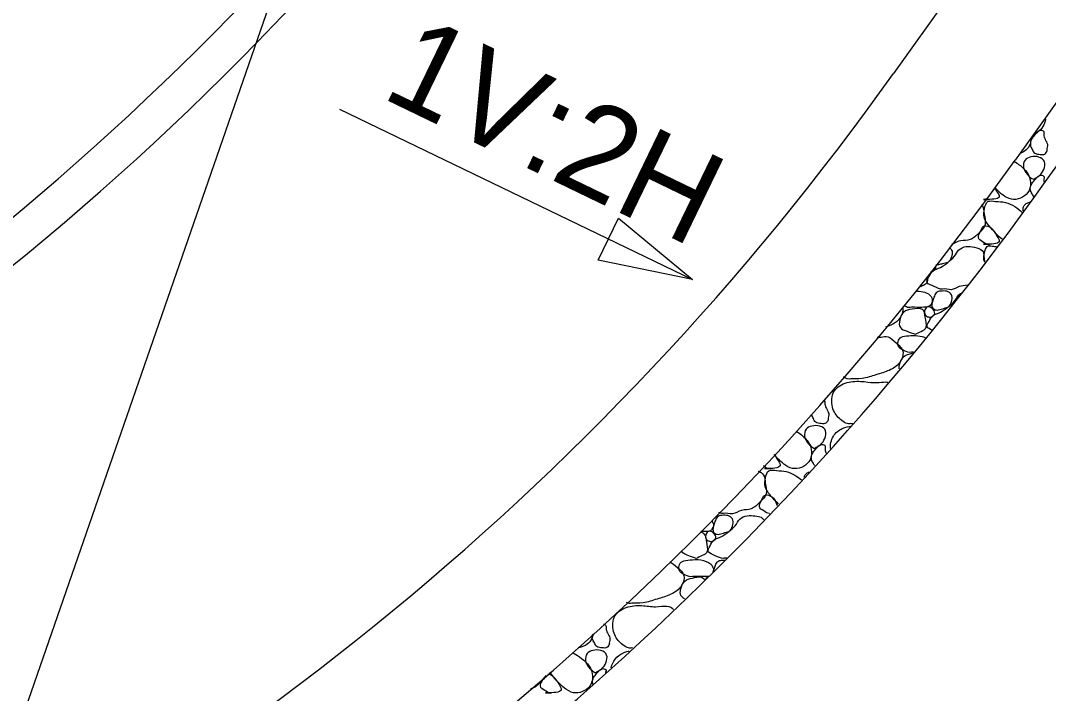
# Model space of a CAD drawing. Extents: x 1385284 to 1385995, y 1975154 to 1975620.
# Drawn here: x 1385446.25 to 1385473.8, y 1975451.07 to 1975469.11 of the extents above; entities that cross this region are included whole.
import ezdxf

# ---------------------------------------------------------------- set-up
doc = ezdxf.new("R2010")
doc.units = 0
for name, color, linetype in [('Default', 7, 'Continuous'), ('R_Horz Alg', 7, 'Continuous'), ('R_Proposed Const Limits', 7, 'Continuous'), ('R_Proposed Road', 7, 'Continuous')]:
    doc.layers.add(name, color=color, linetype=linetype)

msp = doc.modelspace()

# ---------------------------------------------------------------- linework, layer by layer
at = {"layer": 'Default'}
for p, q in [((1385500.579, 1975504.251), (1385472.911, 1975465.371)), ((1385473.726, 1975464.791), (1385501.394, 1975503.671)), ((1385459.101, 1975487.359), (1385417.983, 1975368.797)), ((1385454.799, 1975466.738), (1385464.257, 1975462.164))]:
    msp.add_line(p, q, dxfattribs=at)
msp.add_lwpolyline([(1385462.279, 1975463.815), (1385464.257, 1975462.164), (1385461.734, 1975462.69)], close=True, dxfattribs=at)
for centre, radius, start in [((1385398.122, 1975521.532), 75, 293.41039), ((1385398.122, 1975521.532), 76, 293.41039), ((1385408.545, 1975511.176), 79, 298.55327), ((1385408.545, 1975511.176), 80, 298.5224)]:
    msp.add_arc(centre, radius, start, 324.56338, dxfattribs=at)
for points in [[(1385473.713, 1975466.498), (1385473.731, 1975466.449), (1385473.682, 1975466.305), (1385473.574, 1975466.148), (1385473.47, 1975466.1), (1385473.444, 1975466.09)], [(1385473.771, 1975465.621), (1385473.76, 1975465.596), (1385473.712, 1975465.506), (1385473.59, 1975465.521), (1385473.411, 1975465.54), (1385473.374, 1975465.656), (1385473.299, 1975465.765), (1385473.338, 1975465.929), (1385473.433, 1975466.04), (1385473.51, 1975466.129), (1385473.59, 1975466.185), (1385473.714, 1975466.134), (1385473.671, 1975466.017), (1385473.733, 1975465.891), (1385473.816, 1975465.755), (1385473.752, 1975465.651), (1385473.771, 1975465.621)], [(1385473.444, 1975466.09), (1385473.437, 1975466.071), (1385473.423, 1975466.064), (1385473.405, 1975466.065)], [(1385473.327, 1975465.956), (1385473.339, 1975465.895), (1385473.3, 1975465.726), (1385473.175, 1975465.609), (1385473.064, 1975465.557), (1385473.035, 1975465.546)], [(1385472.883, 1975465.335), (1385472.89, 1975465.33), (1385472.997, 1975465.266), (1385473.196, 1975465.105), (1385473.344, 1975464.846), (1385473.306, 1975464.529), (1385473.12, 1975464.356), (1385472.952, 1975464.312), (1385472.867, 1975464.313)], [(1385473.444, 1975464.887), (1385473.413, 1975464.813), (1385473.209, 1975464.994), (1385473.107, 1975465.173), (1385473.157, 1975465.393), (1385473.321, 1975465.465), (1385473.548, 1975465.473), (1385473.738, 1975465.348), (1385473.687, 1975465.109), (1385473.574, 1975464.945), (1385473.47, 1975464.897), (1385473.444, 1975464.887)], [(1385473.414, 1975464.379), (1385473.396, 1975464.403), (1385473.367, 1975464.465), (1385473.299, 1975464.562), (1385473.338, 1975464.726), (1385473.433, 1975464.837), (1385473.51, 1975464.926), (1385473.59, 1975464.982), (1385473.714, 1975464.931), (1385473.663, 1975464.843), (1385473.687, 1975464.79), (1385473.701, 1975464.758)], [(1385472.354, 1975464.634), (1385472.37, 1975464.599), (1385472.408, 1975464.525), (1385472.59, 1975464.304), (1385471.84, 1975464.321), (1385472.226, 1975464.311), (1385472.218, 1975464.313)], [(1385472.867, 1975464.313), (1385472.796, 1975464.31), (1385472.613, 1975464.394), (1385472.475, 1975464.522), (1385472.385, 1975464.616), (1385472.361, 1975464.643)], [(1385472.012, 1975464.18), (1385472.068, 1975464.103), (1385472.067, 1975463.931), (1385472.152, 1975463.623), (1385471.938, 1975463.416), (1385471.716, 1975463.193), (1385471.44, 1975463.226), (1385471.268, 1975463.126), (1385471.204, 1975463.108), (1385471.202, 1975463.108)], [(1385472.56, 1975463.247), (1385472.515, 1975463.283), (1385472.393, 1975463.4), (1385472.206, 1975463.597), (1385472.048, 1975463.837), (1385472.08, 1975464.063), (1385472.151, 1975464.305), (1385472.38, 1975464.253), (1385472.65, 1975464.258), (1385472.911, 1975464.127), (1385473.041, 1975464.024), (1385473.1, 1975463.963)], [(1385472.184, 1975464.313), (1385472.165, 1975464.313), (1385472.144, 1975464.319), (1385472.124, 1975464.329)], [(1385473.125, 1975463.996), (1385473.124, 1975464), (1385473.114, 1975464.05), (1385473.157, 1975464.19), (1385473.252, 1975464.226), (1385473.31, 1975464.244), (1385473.313, 1975464.245)], [(1385472.184, 1975463.11), (1385472.137, 1975463.109), (1385472.041, 1975463.182), (1385471.878, 1975463.275), (1385471.987, 1975463.46), (1385472.035, 1975463.625), (1385472.216, 1975463.599), (1385472.336, 1975463.494), (1385472.403, 1975463.35), (1385472.59, 1975463.101), (1385471.84, 1975463.118), (1385472.226, 1975463.108), (1385472.218, 1975463.11)], [(1385470.958, 1975461.907), (1385470.887, 1975461.902), (1385470.751, 1975461.982), (1385470.491, 1975462.071), (1385470.605, 1975462.24), (1385470.685, 1975462.427), (1385470.909, 1975462.471), (1385471.11, 1975462.63), (1385471.289, 1975462.772), (1385471.384, 1975462.978), (1385471.595, 1975463.071), (1385471.81, 1975463.045), (1385472.074, 1975462.959), (1385472.062, 1975462.789), (1385472.09, 1975462.668), (1385472.096, 1975462.634)], [(1385471.139, 1975463.024), (1385471.172, 1975463.007), (1385471.238, 1975462.934), (1385471.214, 1975462.774), (1385471.154, 1975462.657), (1385471.101, 1975462.627)], [(1385472.095, 1975462.633), (1385472.09, 1975462.647), (1385472.056, 1975462.724), (1385472.08, 1975462.86), (1385472.151, 1975463.102), (1385472.299, 1975463.056), (1385472.384, 1975463.052), (1385472.411, 1975463.05)], [(1385470.764, 1975462.528), (1385470.787, 1975462.498), (1385470.774, 1975462.436), (1385470.707, 1975462.39), (1385470.673, 1975462.361)], [(1385471.101, 1975462.627), (1385471.054, 1975462.612), (1385470.957, 1975462.589), (1385470.851, 1975462.558), (1385470.793, 1975462.553), (1385470.783, 1975462.553)], [(1385470.551, 1975462.247), (1385470.571, 1975462.18), (1385470.544, 1975462.046), (1385470.417, 1975461.996), (1385470.347, 1975461.962), (1385470.33, 1975461.954)], [(1385470.673, 1975462.361), (1385470.661, 1975462.361), (1385470.65, 1975462.361), (1385470.638, 1975462.361)], [(1385471.63, 1975462.016), (1385471.549, 1975462.003), (1385471.402, 1975462.002), (1385471.203, 1975461.848), (1385471.037, 1975461.927), (1385470.958, 1975461.907)], [(1385470.259, 1975461.86), (1385470.298, 1975461.858), (1385470.44, 1975461.849), (1385470.652, 1975461.768), (1385470.711, 1975461.582), (1385470.615, 1975461.416), (1385470.41, 1975461.423), (1385470.249, 1975461.418), (1385470.13, 1975461.424)], [(1385470.682, 1975460.807), (1385470.628, 1975460.836), (1385470.507, 1975460.89), (1385470.605, 1975461.037), (1385470.685, 1975461.224), (1385470.909, 1975461.268), (1385471.11, 1975461.427), (1385471.289, 1975461.569), (1385471.363, 1975461.736), (1385471.44, 1975461.788), (1385471.468, 1975461.803)], [(1385471.101, 1975461.424), (1385471.054, 1975461.409), (1385470.957, 1975461.386), (1385470.823, 1975461.332), (1385470.696, 1975461.374), (1385470.669, 1975461.48), (1385470.699, 1975461.594), (1385470.743, 1975461.721), (1385470.803, 1975461.846), (1385470.954, 1975461.862), (1385471.126, 1975461.858), (1385471.238, 1975461.731), (1385471.214, 1975461.571), (1385471.154, 1975461.454), (1385471.101, 1975461.424)], [(1385469.89, 1975461.418), (1385469.916, 1975461.315), (1385469.825, 1975461.1), (1385469.63, 1975460.956), (1385469.5, 1975460.907), (1385469.438, 1975460.886)], [(1385470.235, 1975460.704), (1385470.163, 1975460.714), (1385470.018, 1975460.783), (1385469.795, 1975460.854), (1385469.798, 1975461.082), (1385469.908, 1975461.328), (1385470.124, 1975461.377), (1385470.485, 1975461.407), (1385470.488, 1975461.165), (1385470.57, 1975460.854), (1385470.386, 1975460.776), (1385470.283, 1975460.728), (1385470.235, 1975460.704)], [(1385470.13, 1975461.424), (1385470.074, 1975461.4), (1385469.999, 1975461.431), (1385469.935, 1975461.463), (1385469.93, 1975461.466)], [(1385470.673, 1975461.158), (1385470.636, 1975461.158), (1385470.551, 1975461.156), (1385470.472, 1975461.237), (1385470.48, 1975461.355), (1385470.564, 1975461.458), (1385470.691, 1975461.407), (1385470.795, 1975461.247), (1385470.707, 1975461.187), (1385470.673, 1975461.158)], [(1385469.212, 1975460.619), (1385469.217, 1975460.619), (1385469.305, 1975460.613), (1385469.506, 1975460.676), (1385469.709, 1975460.471), (1385469.962, 1975460.267), (1385469.836, 1975459.906), (1385469.547, 1975459.716), (1385469.179, 1975459.616), (1385468.808, 1975459.487), (1385468.574, 1975459.502), (1385468.502, 1975459.505)], [(1385470.13, 1975460.221), (1385470.074, 1975460.197), (1385469.929, 1975460.255), (1385469.768, 1975460.341), (1385469.757, 1975460.508), (1385469.834, 1975460.639), (1385470.053, 1975460.658), (1385470.293, 1975460.677), (1385470.468, 1975460.624), (1385470.509, 1975460.603)], [(1385469.8, 1975459.767), (1385469.795, 1975459.799), (1385469.808, 1975459.907), (1385469.908, 1975460.125), (1385470.063, 1975460.161), (1385470.151, 1975460.189), (1385470.161, 1975460.192)], [(1385470.184, 1975460.219), (1385470.166, 1975460.219), (1385470.148, 1975460.22), (1385470.13, 1975460.221)], [(1385468.502, 1975458.302), (1385468.434, 1975458.268), (1385468.211, 1975458.405), (1385467.996, 1975458.65), (1385467.967, 1975459.168), (1385468.344, 1975459.424), (1385468.78, 1975459.453), (1385469.14, 1975459.38), (1385469.403, 1975459.431), (1385469.491, 1975459.413), (1385469.498, 1975459.411)], [(1385468.502, 1975459.505), (1385468.447, 1975459.477), (1385468.373, 1975459.511), (1385468.309, 1975459.555)], [(1385467.776, 1975458.926), (1385467.782, 1975458.921), (1385467.821, 1975458.894), (1385467.802, 1975458.799), (1385467.864, 1975458.673), (1385467.946, 1975458.537), (1385467.883, 1975458.433), (1385467.901, 1975458.403)], [(1385467.901, 1975458.403), (1385467.891, 1975458.378), (1385467.843, 1975458.288), (1385467.721, 1975458.303), (1385467.542, 1975458.322), (1385467.505, 1975458.437), (1385467.466, 1975458.509), (1385467.453, 1975458.545)], [(1385467.044, 1975458.098), (1385467.138, 1975458.04), (1385467.328, 1975457.884), (1385467.474, 1975457.628), (1385467.436, 1975457.311), (1385467.251, 1975457.138), (1385467.082, 1975457.094), (1385466.998, 1975457.095)], [(1385467.575, 1975457.669), (1385467.544, 1975457.595), (1385467.339, 1975457.776), (1385467.237, 1975457.955), (1385467.288, 1975458.175), (1385467.452, 1975458.248), (1385467.679, 1975458.255), (1385467.869, 1975458.13), (1385467.818, 1975457.892), (1385467.705, 1975457.727), (1385467.601, 1975457.679), (1385467.575, 1975457.669)], [(1385467.97, 1975457.62), (1385467.942, 1975457.727), (1385468.014, 1975458.002), (1385468.27, 1975458.188), (1385468.465, 1975458.228), (1385468.499, 1975458.233)], [(1385468.555, 1975458.299), (1385468.537, 1975458.3), (1385468.52, 1975458.301), (1385468.502, 1975458.302)], [(1385467.54, 1975457.168), (1385467.525, 1975457.19), (1385467.497, 1975457.25), (1385467.43, 1975457.344), (1385467.469, 1975457.508), (1385467.564, 1975457.62), (1385467.64, 1975457.708), (1385467.72, 1975457.764), (1385467.845, 1975457.713), (1385467.798, 1975457.609), (1385467.832, 1975457.542), (1385467.85, 1975457.494)], [(1385466.453, 1975457.476), (1385466.486, 1975457.422), (1385466.534, 1975457.333), (1385466.721, 1975457.086), (1385465.971, 1975457.103), (1385466.357, 1975457.093), (1385466.349, 1975457.095)], [(1385466.998, 1975457.095), (1385466.926, 1975457.092), (1385466.744, 1975457.176), (1385466.589, 1975457.32), (1385466.487, 1975457.429), (1385466.449, 1975457.472)], [(1385466.025, 1975457.027), (1385466.066, 1975457.02), (1385466.203, 1975456.932), (1385466.197, 1975456.716), (1385466.283, 1975456.405), (1385466.069, 1975456.198), (1385465.847, 1975455.976), (1385465.57, 1975456.008), (1385465.333, 1975455.833), (1385465.168, 1975455.912), (1385465.089, 1975455.892)], [(1385466.315, 1975457.095), (1385466.268, 1975457.094), (1385466.215, 1975457.133), (1385466.165, 1975457.169), (1385466.163, 1975457.171)], [(1385466.566, 1975456.144), (1385466.487, 1975456.224), (1385466.336, 1975456.379), (1385466.178, 1975456.619), (1385466.21, 1975456.845), (1385466.281, 1975457.087), (1385466.51, 1975457.035), (1385466.78, 1975457.04), (1385467.018, 1975456.92), (1385467.137, 1975456.832), (1385467.182, 1975456.792)], [(1385467.254, 1975456.868), (1385467.259, 1975456.891), (1385467.298, 1975456.96), (1385467.35, 1975456.992), (1385467.387, 1975457.007)], [(1385466.315, 1975455.892), (1385466.268, 1975455.891), (1385466.172, 1975455.964), (1385466.009, 1975456.057), (1385466.118, 1975456.242), (1385466.166, 1975456.407), (1385466.347, 1975456.381), (1385466.466, 1975456.276), (1385466.505, 1975456.164), (1385466.529, 1975456.106), (1385466.529, 1975456.106)], [(1385465.089, 1975455.892), (1385465.049, 1975455.889), (1385465.009, 1975455.899), (1385464.969, 1975455.916)], [(1385466.328, 1975455.894), (1385466.322, 1975455.894), (1385466.303, 1975455.893), (1385466.319, 1975455.891), (1385466.325, 1975455.891)], [(1385464.762, 1975455.698), (1385464.762, 1975455.698), (1385464.812, 1975455.647), (1385464.842, 1975455.567), (1385464.746, 1975455.401), (1385464.615, 1975455.409), (1385464.53, 1975455.407), (1385464.485, 1975455.407)], [(1385465.089, 1975454.689), (1385465.017, 1975454.684), (1385464.882, 1975454.764), (1385464.622, 1975454.854), (1385464.736, 1975455.022), (1385464.815, 1975455.209), (1385465.04, 1975455.254), (1385465.24, 1975455.412), (1385465.419, 1975455.554), (1385465.514, 1975455.76), (1385465.726, 1975455.853), (1385465.941, 1975455.827), (1385466.117, 1975455.803), (1385466.157, 1975455.738), (1385466.165, 1975455.723)], [(1385465.231, 1975455.409), (1385465.184, 1975455.394), (1385465.088, 1975455.371), (1385464.953, 1975455.317), (1385464.827, 1975455.359), (1385464.8, 1975455.465), (1385464.83, 1975455.579), (1385464.873, 1975455.706), (1385464.934, 1975455.831), (1385465.084, 1975455.847), (1385465.256, 1975455.843), (1385465.369, 1975455.716), (1385465.345, 1975455.556), (1385465.284, 1975455.439), (1385465.231, 1975455.409)], [(1385464.481, 1975455.403), (1385464.504, 1975455.397), (1385464.622, 1975455.321), (1385464.619, 1975455.15), (1385464.701, 1975454.839), (1385464.517, 1975454.762), (1385464.414, 1975454.713), (1385464.365, 1975454.689)], [(1385464.804, 1975455.143), (1385464.766, 1975455.143), (1385464.682, 1975455.141), (1385464.602, 1975455.223), (1385464.611, 1975455.341), (1385464.695, 1975455.443), (1385464.822, 1975455.392), (1385464.925, 1975455.232), (1385464.838, 1975455.172), (1385464.804, 1975455.143)], [(1385464.365, 1975454.689), (1385464.293, 1975454.699), (1385464.149, 1975454.768), (1385464.017, 1975454.813), (1385463.963, 1975454.879), (1385463.959, 1975454.884)], [(1385463.65, 1975454.593), (1385463.715, 1975454.568), (1385463.85, 1975454.445), (1385464.092, 1975454.252), (1385463.967, 1975453.892), (1385463.678, 1975453.701), (1385463.31, 1975453.601), (1385462.938, 1975453.472), (1385462.705, 1975453.487), (1385462.633, 1975453.49)], [(1385464.26, 1975454.206), (1385464.205, 1975454.182), (1385464.06, 1975454.24), (1385463.898, 1975454.326), (1385463.888, 1975454.493), (1385463.965, 1975454.625), (1385464.184, 1975454.643), (1385464.484, 1975454.673), (1385464.782, 1975454.55), (1385464.831, 1975454.376), (1385464.818, 1975454.32), (1385464.818, 1975454.318)], [(1385464.814, 1975454.314), (1385464.82, 1975454.339), (1385464.838, 1975454.4), (1385464.873, 1975454.503), (1385464.934, 1975454.628), (1385465.041, 1975454.638), (1385465.106, 1975454.641), (1385465.134, 1975454.639)], [(1385465.184, 1975454.691), (1385465.151, 1975454.695), (1385465.119, 1975454.697), (1385465.089, 1975454.689)], [(1385464.055, 1975453.602), (1385464.026, 1975453.618), (1385463.925, 1975453.678), (1385463.928, 1975453.864), (1385464.038, 1975454.11), (1385464.254, 1975454.159), (1385464.503, 1975454.225), (1385464.581, 1975454.128), (1385464.593, 1975454.107)], [(1385464.698, 1975454.206), (1385464.672, 1975454.205), (1385464.526, 1975454.205), (1385464.38, 1975454.2), (1385464.26, 1975454.206)], [(1385464.618, 1975454.13), (1385464.619, 1975454.132), (1385464.636, 1975454.165), (1385464.665, 1975454.197), (1385464.699, 1975454.209), (1385464.703, 1975454.211)], [(1385462.633, 1975452.287), (1385462.565, 1975452.253), (1385462.342, 1975452.39), (1385462.127, 1975452.635), (1385462.097, 1975453.153), (1385462.474, 1975453.409), (1385462.911, 1975453.438), (1385463.27, 1975453.365), (1385463.598, 1975453.442), (1385463.71, 1975453.36), (1385463.754, 1975453.32)], [(1385462.633, 1975453.49), (1385462.593, 1975453.47), (1385462.542, 1975453.482), (1385462.493, 1975453.508)], [(1385461.877, 1975452.929), (1385461.893, 1975452.924), (1385461.965, 1975452.891), (1385461.933, 1975452.784), (1385461.995, 1975452.658), (1385462.077, 1975452.522), (1385462.013, 1975452.418), (1385462.032, 1975452.388)], [(1385461.594, 1975452.664), (1385461.595, 1975452.62), (1385461.549, 1975452.481), (1385461.402, 1975452.346), (1385461.256, 1975452.296), (1385461.193, 1975452.287)], [(1385462.032, 1975452.388), (1385462.022, 1975452.363), (1385461.974, 1975452.273), (1385461.851, 1975452.288), (1385461.673, 1975452.307), (1385461.635, 1975452.423), (1385461.566, 1975452.527), (1385461.571, 1975452.618), (1385461.588, 1975452.658)], [(1385462.652, 1975452.286), (1385462.645, 1975452.286), (1385462.639, 1975452.287), (1385462.633, 1975452.287)], [(1385461.049, 1975452.153), (1385461.089, 1975452.134), (1385461.233, 1975452.055), (1385461.457, 1975451.872), (1385461.605, 1975451.613), (1385461.567, 1975451.296), (1385461.381, 1975451.124), (1385461.213, 1975451.079), (1385461.128, 1975451.08)], [(1385461.706, 1975451.654), (1385461.675, 1975451.58), (1385461.47, 1975451.761), (1385461.368, 1975451.94), (1385461.419, 1975452.16), (1385461.583, 1975452.233), (1385461.81, 1975452.24), (1385462, 1975452.115), (1385461.948, 1975451.877), (1385461.835, 1975451.712), (1385461.731, 1975451.664), (1385461.706, 1975451.654)], [(1385462.083, 1975451.753), (1385462.086, 1975451.81), (1385462.184, 1975452.017), (1385462.38, 1975452.164), (1385462.554, 1975452.204), (1385462.567, 1975452.207)], [(1385461.597, 1975451.296), (1385461.591, 1975451.308), (1385461.564, 1975451.361), (1385461.6, 1975451.493), (1385461.694, 1975451.605), (1385461.771, 1975451.693), (1385461.851, 1975451.749), (1385461.976, 1975451.698), (1385461.917, 1975451.638), (1385461.926, 1975451.611), (1385461.928, 1975451.607)], [(1385460.33, 1975451.54), (1385460.294, 1975451.479), (1385460.179, 1975451.363), (1385460.054, 1975451.23), (1385459.948, 1975451.2), (1385459.916, 1975451.194)], [(1385460.446, 1975451.08), (1385460.398, 1975451.079), (1385460.302, 1975451.152), (1385460.14, 1975451.245), (1385460.24, 1975451.415), (1385460.295, 1975451.505), (1385460.338, 1975451.548)], [(1385460.38, 1975451.583), (1385460.4, 1975451.594), (1385460.479, 1975451.568), (1385460.597, 1975451.464), (1385460.664, 1975451.32), (1385460.851, 1975451.071), (1385460.102, 1975451.088), (1385460.488, 1975451.078), (1385460.48, 1975451.08)], [(1385461.128, 1975451.08), (1385461.057, 1975451.077), (1385460.874, 1975451.161), (1385460.678, 1975451.343), (1385460.531, 1975451.507), (1385460.455, 1975451.617), (1385460.443, 1975451.635)]]:
    msp.add_open_spline(points, degree=3, dxfattribs=at)
at = {"layer": 'R_Horz Alg'}
msp.add_arc((1385514.357, 1974795.066), 694.494, 77.498258, 106.635112, dxfattribs=at)
at = {"layer": 'R_Proposed Const Limits'}
msp.add_line((1385497.32, 1975506.57), (1385469.652, 1975467.69), dxfattribs=at)
msp.add_arc((1385408.545, 1975511.176), 75, 293.41039, 324.56338, dxfattribs=at)
at = {"layer": 'R_Proposed Road'}
msp.add_arc((1385514.357, 1974795.066), 683.494, 77.498258, 106.910819, dxfattribs=at)

# ---------------------------------------------------------------- texts
at = {"layer": 'Default'}
msp.add_text('1V:2H', height=2.5, rotation=334.1902, dxfattribs=at).set_placement((1385455.873, 1975467.068))

doc.saveas('drawing.dxf')
